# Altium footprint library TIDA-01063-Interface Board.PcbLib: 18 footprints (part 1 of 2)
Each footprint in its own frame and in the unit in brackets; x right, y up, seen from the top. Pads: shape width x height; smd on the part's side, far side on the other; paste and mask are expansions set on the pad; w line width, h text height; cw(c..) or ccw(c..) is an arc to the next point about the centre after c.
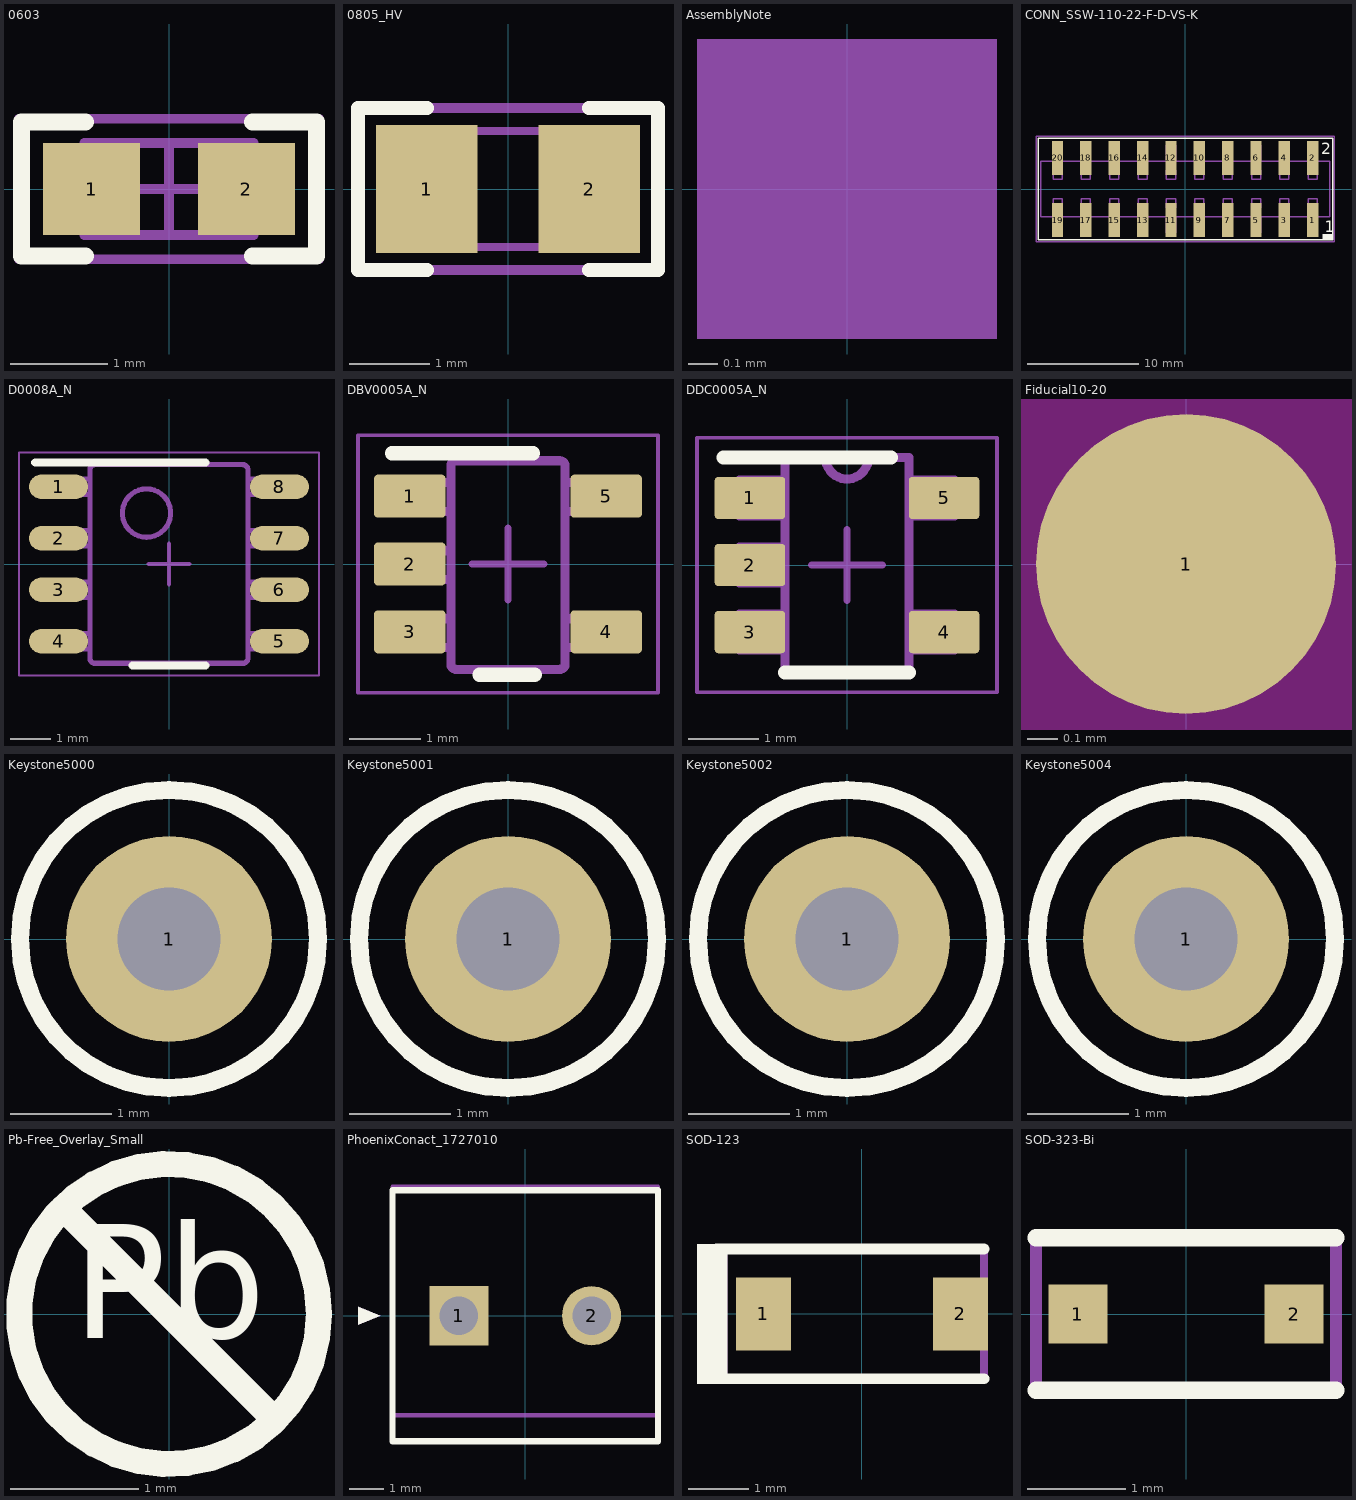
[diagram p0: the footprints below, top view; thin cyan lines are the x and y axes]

## 0603 [mm] "0603 from SM-752 data"
height 1
pads (2):
  rect 1x0.95 smd: 1(-0.8,0) 2(0.8,0)
Top Overlay:
  lines w0.178: -0.864,-0.691 -1.524,-0.691 -1.524,0.693 -0.864,0.693 ; 0.864,-0.691 1.524,-0.691 1.524,0.693 0.864,0.693
Mechanical 5:
  lines w0.1: -1.55,-0.725 1.55,-0.725 1.55,0.725 -1.55,0.725 -1.55,-0.725
  text ".Designator" at -1.397,-0.381 h0.76
Mechanical 13:
  lines w0.1: -0.55,-0.475 -0.55,0.475 ; 0.55,-0.475 0.55,0.475 ; -0.875,-0.475 -0.875,0.475 0.875,0.475 0.875,-0.475 -0.875,-0.475
Mechanical 15:
  lines w0.1: -0.475,0 0.475,0 ; 0,-0.475 0,0.475 ; -1.55,-0.725 -1.55,0.725 1.55,0.725 1.55,-0.725 -1.55,-0.725
3D body: height 1, standoff 0, extent 0.551,-0.474 0.874,0.474
3D body: height 1, standoff 0, extent -0.549,-0.474 0.549,0.474
3D body: height 1, standoff 0, extent -0.874,-0.474 -0.551,0.474

## 0805_HV [mil] "0805 with 30mil clearance between pads"
height 57.09
pads (2):
  rect 50x63 smd: 1(-40,0) 2(40,0)
Top Overlay:
  lines w7: -40,-40 -74,-40 -74,0 -74,40 -40,40 ; 40,-40 74,-40 74,0 74,40 40,40
Mechanical 5:
  lines w5: -74,-40 -74,40 74,40 74,-40 -74,-40
  text ".Designator" at -64,-17 h35
Mechanical 13:
  lines w3.94: -25.59,-28.54 -25.59,28.54 ; 25.59,-28.54 25.59,28.54 ; -43.31,-28.54 -43.31,28.54 43.31,28.54 43.31,-28.54 -43.31,-28.54
3D body: height 57.09, standoff 0, extent 25.61,-28.52 43.29,28.52
3D body: height 57.09, standoff 0, extent -25.57,-28.52 25.57,28.52
3D body: height 57.09, standoff 0, extent -43.29,-28.52 -25.61,28.52

## AssemblyNote [mil] "Assembly Note"
Mechanical 5:
  rectangle: -20,-20 20,20
  text ".Comment" at 45,-20 h40
  text ".Designator" at -165,-20 h40

## CONN_SSW-110-22-F-D-VS-K [mil]
pads (20):
  rect 40x120 smd: 1(450,-110) 2(450,110) 3(350,-110) 4(350,110) 5(250,-110) 6(250,110) 7(150,-110) 8(150,110) 9(50,-110) 10(50,110) 11(-50,-110) 12(-50,110) 13(-150,-110) 14(-150,110) 15(-250,-110) 16(-250,110) 17(-350,-110) 18(-350,110) 19(-450,-110) 20(-450,110)
Top Overlay:
  region: 518,-160 518,-178 485,-178 485,-160
  lines w5: -518,-178.15 519.68,-178.15 519.68,179.13 -518,179.13 -518,-178.15
  text "1" at 492,-153 h40
  text "2" at 480.31,122.05 h40
Mechanical 5:
  drawing of 156 lines, arcs and shapes, not listed
  text ".Designator" at -95,-20 h40
  text "1" at 492,-153 h40
  text "2" at 480.31,122.05 h40
Mechanical 15:
  lines w5: -526,-186 526,-186 526,186 -526,186 -526,-186
3D body: height 435.04, standoff 0, extent -510,-154.92 500,154.93

## D0008A_N [mm] "SOIC, 8-Leads, Body 4.9x3.9mm, Pitch 1.27mm, IPC Medium Density"
height 1.75
pads (8):
  oval 1.45x0.6 smd: 1(-2.725,1.905) 2(-2.725,0.635) 3(-2.725,-0.635) 4(-2.725,-1.905) 5(2.725,-1.905) 6(2.725,-0.635) 7(2.725,0.635) 8(2.725,1.905)
Top Overlay:
  lines w0.2: -3.3,2.5 0.9,2.5 ; -0.9,-2.5 0.9,-2.5
Mechanical 5:
  lines w0.127: -2.375,-2.095 -1.995,-2.095 -1.952,-2.095 -1.952,-1.715 -1.995,-1.715 -2.375,-1.715 ; -2.375,-2.095 -2.589,-2.095 -3.002,-2.095 -3.002,-1.715 -2.589,-1.715 -2.375,-1.715 ; -2.375,-2.095 -2.375,-1.715 ; -2.375,-0.825 -1.995,-0.825 -1.952,-0.825 -1.952,-0.445 -1.995,-0.445 -2.375,-0.445 ; -2.375,-0.825 -2.589,-0.825 -3.002,-0.825 -3.002,-0.445 -2.589,-0.445 -2.375,-0.445 ; -2.375,-0.825 -2.375,-0.445 ; -2.375,0.445 -1.995,0.445 -1.952,0.445 -1.952,0.825 -1.995,0.825 -2.375,0.825 ; -2.375,0.445 -2.589,0.445 -3.002,0.445 -3.002,0.825 -2.589,0.825 -2.375,0.825 ; -2.375,0.445 -2.375,0.825 ; -2.375,1.715 -1.995,1.715 -1.952,1.715 -1.952,2.095 -1.995,2.095 -2.375,2.095 ; -2.375,1.715 -2.589,1.715 -3.002,1.715 -3.002,2.095 -2.589,2.095 -2.375,2.095 ; -2.375,1.715 -2.375,2.095 ; -0.332,-2.45 -1.825,-2.45 -1.826,-2.45 cw(c-1.825,-2.323) -1.952,-2.324 -1.952,-2.323 -1.952,2.323 -1.952,2.324 cw(c-1.825,2.323) -1.826,2.45 -1.825,2.45 -0.332,2.45 ; -0.332,-2.45 -0.182,-2.45 ; -0.332,-2.45 -0.182,-2.45 ; -0.332,2.45 -0.182,2.45 ; -0.332,2.45 -0.182,2.45 ; -0.182,-2.45 0.178,-2.45 ; -0.182,2.45 0.178,2.45 ; 0.178,-2.45 0.328,-2.45 ; 0.178,-2.45 0.328,-2.45 ; 0.178,2.45 0.328,2.45 ; 0.178,2.45 0.328,2.45 ; 0.328,-2.45 1.821,-2.45 1.822,-2.45 ccw(c1.821,-2.323) 1.948,-2.324 1.948,-2.323 1.948,2.323 1.948,2.324 ccw(c1.821,2.323) 1.822,2.45 1.821,2.45 0.328,2.45 ; 2.371,-2.095 2.585,-2.095 2.998,-2.095 2.998,-1.715 2.585,-1.715 2.371,-1.715 ; 2.371,-2.095 1.991,-2.095 1.948,-2.095 1.948,-1.715 1.991,-1.715 2.371,-1.715 ; 2.371,-2.095 2.371,-1.715 ; 2.371,-0.825 2.585,-0.825 2.998,-0.825 2.998,-0.445 2.585,-0.445 2.371,-0.445 ; 2.371,-0.825 1.991,-0.825 1.948,-0.825 1.948,-0.445 1.991,-0.445 2.371,-0.445 ; 2.371,-0.825 2.371,-0.445 ; 2.371,0.445 2.585,0.445 2.998,0.445 2.998,0.825 2.585,0.825 2.371,0.825 ; 2.371,0.445 1.991,0.445 1.948,0.445 1.948,0.825 1.991,0.825 2.371,0.825 ; 2.371,0.445 2.371,0.825 ; 2.371,1.715 2.585,1.715 2.998,1.715 2.998,2.095 2.585,2.095 2.371,2.095 ; 2.371,1.715 1.991,1.715 1.948,1.715 1.948,2.095 1.991,2.095 2.371,2.095 ; 2.371,1.715 2.371,2.095 ; -0.555,0.659 cw(c-0.555,1.256) -0.555,1.853 cw(c-0.555,1.256) -0.555,0.659
  text ".Designator" at -1.625,-0.625 h0.89
Mechanical 15:
  lines w0.05: -3.7,-2.75 3.7,-2.75 3.7,2.75 -3.7,2.75 -3.7,-2.75
  lines w0.1: -0.5,0 0.5,0 ; 0,-0.5 0,0.5
3D body: height 1.63, standoff 0, extent -3,-2.45 3,2.45

## DBV0005A_N [mm] "SOT23, 5-Leads, Body 2.9x1.6mm, Pitch 0.95mm, Lead Span 2.8mm, IPC Medium Density"
height 1.45
pads (5):
  rrect17% 1x0.6 smd: 1(-1.375,0.95) 2(-1.375,0) 3(-1.375,-0.95) 4(1.375,-0.95) 5(1.375,0.95)
Top Overlay:
  lines w0.2: -1.625,1.55 0.35,1.55 ; -0.4,-1.55 0.375,-1.55
Mechanical 5:
  lines w0.127: -0.801,1.371 cw(c-0.725,1.37) -0.725,1.446 ; -0.801,1.37 -0.801,1.371 ; -0.801,1.37 -0.801,-1.399 -0.801,-1.4 ccw(c-0.725,-1.399) -0.725,-1.475 ; -0.725,-1.475 0.723,-1.475 0.724,-1.475 ccw(c0.723,-1.399) 0.799,-1.4 0.799,-1.399 0.799,1.37 ; -0.725,-1.475 -0.725,-1.475 ; -0.725,1.446 -0.725,1.446 ; -0.725,1.446 0.723,1.446 0.724,1.446 cw(c0.723,1.37) 0.799,1.371 ; 0.799,1.37 0.799,1.371 ; -1.423,-1.167 -1.423,-0.767 -1.199,-0.767 -1.105,-0.767 -1.088,-0.767 -0.835,-0.767 -0.801,-0.767 -0.801,-1.167 -0.835,-1.167 -1.088,-1.167 -1.105,-1.167 -1.199,-1.167 -1.423,-1.167 ; -1.423,-0.215 -1.423,0.186 -1.199,0.186 -1.105,0.186 -1.088,0.186 -0.835,0.186 -0.801,0.186 -0.801,-0.215 -0.835,-0.215 -1.088,-0.215 -1.105,-0.215 -1.199,-0.215 -1.423,-0.215 ; -1.423,0.738 -1.423,1.138 -1.199,1.138 -1.105,1.138 -1.088,1.138 -0.835,1.138 -0.801,1.138 -0.801,0.738 -0.835,0.738 -1.088,0.738 -1.105,0.738 -1.199,0.738 -1.423,0.738 ; 0.799,-1.167 0.834,-1.167 1.087,-1.167 1.103,-1.167 1.198,-1.167 1.422,-1.167 1.422,-0.767 1.198,-0.767 1.103,-0.767 1.087,-0.767 0.834,-0.767 0.799,-0.767 0.799,-1.167 ; 0.799,0.738 0.834,0.738 1.087,0.738 1.103,0.738 1.198,0.738 1.422,0.738 1.422,1.138 1.198,1.138 1.103,1.138 1.087,1.138 0.834,1.138 0.799,1.138 0.799,0.738
  text ".Designator" at -0.25,0.95 h0.51
Mechanical 15:
  lines w0.05: -2.1,-1.8 -2.1,1.8 2.1,1.8 2.1,-1.8 -2.1,-1.8
  lines w0.1: -0.5,0 0.5,0 ; 0,-0.5 0,0.5
3D body: height 1.09, standoff 0, extent -1.422,-1.461 1.423,1.46

## DDC0005A_N [mm]
height 1.1
pads (5):
  rrect17% 1x0.6 smd: 1(-1.375,0.95) 2(-1.375,0) 3(-1.375,-0.95) 4(1.375,-0.95) 5(1.375,0.95)
Top Overlay:
  lines w0.2: -1.75,1.525 0.625,1.525 ; -0.876,-1.524 0.876,-1.524
Mechanical 5:
  lines w0.127: -0.305,1.524 ccw(c0,1.524) 0.305,1.524 ; -1.524,-1.204 -1.524,-0.696 -0.876,-0.696 -0.876,-1.204 -1.524,-1.204 ; -1.524,-0.254 -1.524,0.254 -0.876,0.254 -0.876,-0.254 -1.524,-0.254 ; -1.524,0.696 -1.524,1.204 -0.876,1.204 -0.876,0.696 -1.524,0.696 ; -0.876,-1.524 0.876,-1.524 0.876,1.524 -0.876,1.524 -0.876,-1.524 ; 0.876,-1.204 0.876,-0.696 1.524,-0.696 1.524,-1.204 0.876,-1.204 ; 0.876,0.696 0.876,1.204 1.524,1.204 1.524,0.696 0.876,0.696
  text ".Designator" at -0.35,1.075 h0.6
Mechanical 15:
  lines w0.05: -2.125,-1.8 2.125,-1.8 2.125,1.8 -2.125,1.8 -2.125,-1.8
  lines w0.1: -0.5,0 0.5,0 ; 0,-0.5 0,0.5
3D body: height 1.1, standoff 0, extent -1.405,-1.45 1.406,1.45

## Fiducial10-20 [mm]
pads (1):
  round 1 smd mask+0.5: 1(0,0)
Top Layer keep-out:
  circle w1.178: c0,0 r0.5

## Keystone5000 [mil] "For Keystone 500x miniature loop terminals"
height 181.1
pads (1):
  round 80 hole 40: 1(0,0)
Top Overlay:
  circle w7: c0,0 r58
Mechanical 5:
  circle w5: c0,0 r58.31
  text ".Designator" at -45,-10 h30
3D body: height 181.97, standoff -118.11, extent -49,-49 49.04,49.24

## Keystone5001 [mil] "For Keystone 500x miniature loop terminals"
height 181.1
pads (1):
  round 80 hole 40: 1(0,0)
Top Overlay:
  circle w7: c0,0 r58
Mechanical 5:
  circle w5: c0,0 r58.31
  text ".Designator" at -45,-10 h30
3D body: height 181.97, standoff -118.11, extent -49,-49 49.04,49.24

## Keystone5002 [mil] "For Keystone 500x miniature loop terminals"
height 181.1
pads (1):
  round 80 hole 40: 1(0,0)
Top Overlay:
  circle w7: c0,0 r58
Mechanical 5:
  circle w5: c0,0 r58.31
  text ".Designator" at -45,-10 h30
3D body: height 181.97, standoff -118.11, extent -49,-49 49.04,49.23

## Keystone5004 [mil] "For Keystone 500x miniature loop terminals"
height 181.1
pads (1):
  round 80 hole 40: 1(0,0)
Top Overlay:
  circle w7: c0,0 r58
Mechanical 5:
  circle w5: c0,0 r58.31
  text ".Designator" at -45,-10 h30
3D body: height 181.97, standoff -118.11, extent -49,-49 49.04,49.24

## Pb-Free_Overlay_Small [mil]
Top Overlay:
  circle w8: c0,0 r46
  lines w8: -32.53,32.53 32.53,-32.53
  text "Pb" at -29.6,-18.9 h60

## PhoenixConact_1727010 [mm]
height 8.5
pads (2):
  rect 1.7x1.7 hole 1.1: 1(-1.905,0)
  round 1.7 hole 1.1: 2(1.905,0)
Top Overlay:
  region: -4.8,-0.254 -4.8,0.254 -4.165,0
  lines w0.178: -3.81,-3.6 0,-3.6 3.81,-3.6 3.81,0 3.81,3.6 0,3.6 -3.81,3.6 -3.81,0 -3.81,-3.6
Mechanical 5:
  region: -4.8,-0.254 -4.8,0.254 -4.165,0
  lines w0.127: -3.81,-2.861 3.81,-2.861 ; -3.81,-2.861 -3.81,-3.3 -3.81,-3.6 3.81,-3.6 3.81,-3.3 3.81,-2.861 ; -3.81,-2.861 -3.81,-2.049 -3.81,-1.566 -3.81,1.487 -3.81,1.962 -3.81,3.7 3.81,3.7 3.81,1.962 3.81,1.487 3.81,-1.566 3.81,-2.049 3.81,-2.861
  text ".Designator" at -1.524,-0.508 h1.02
3D body: height 8.52, standoff -3.48, extent -3.81,-3.599 3.81,3.701

## SOD-123 [mm] "On Semi recommended land pattern"
height 1.35
pads (2):
  rect 0.915x1.22 smd: 1(-1.637,0) 2(1.637,0)
Top Overlay:
  rectangle: -2.743,-1.169 -2.235,1.168
  lines w0.178: -2.413,-1.079 2.032,-1.079 ; -2.413,1.079 2.032,1.079
Mechanical 5:
  rectangle: -2.743,-1.169 -2.235,1.168
  lines w0.127: -2.413,-1.079 2.032,-1.079 2.032,1.079 -2.413,1.079
  text ".Designator" at -1.956,-0.33 h0.76
3D body: height 1.35, standoff 0, extent -1.932,-0.9 1.932,0.9

## SOD-323-Bi [mm] "SOD323, 2-Leads, Body 1.9x1.45mm, No Polarity Mark"
height 1.1
pads (2):
  rect 0.6x0.6 smd paste-0.05: 1(-1.1,0) 2(1.1,0)
Top Overlay:
  lines w0.178: -1.525,-0.775 0.1,-0.775 1.525,-0.775 ; -1.525,0.775 0.1,0.775 1.525,0.775
Mechanical 5:
  lines w0.127: -1.525,-0.775 0.1,-0.775 1.525,-0.775 1.525,0.775 0.1,0.775 -1.525,0.775 -1.525,-0.775
  text ".Designator" at -1.4,-0.275 h0.76
3D body: height 1.02, standoff 0.01, extent -1.273,-0.65 1.273,0.65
